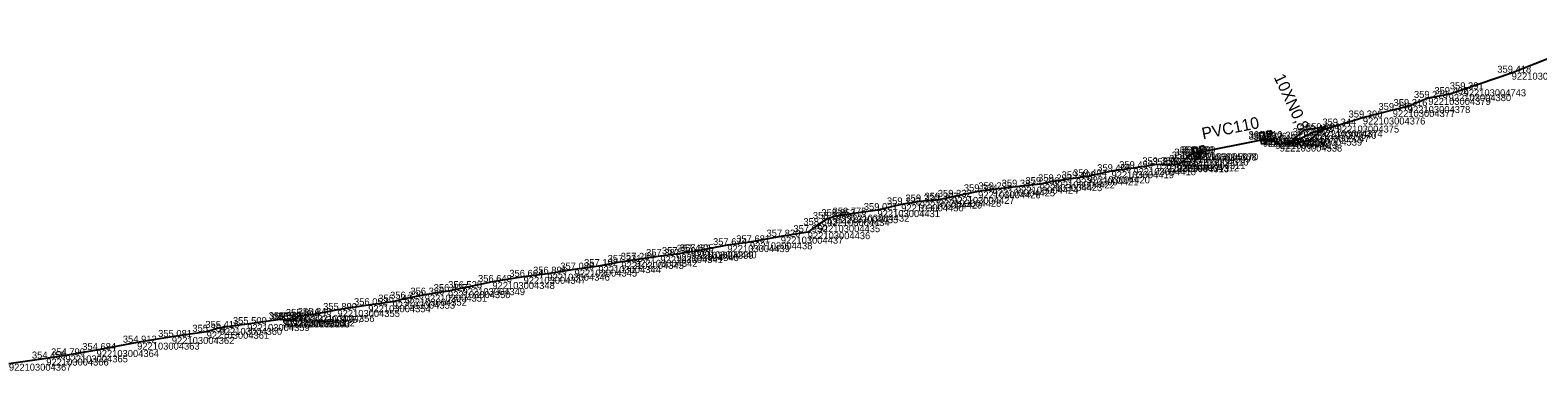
# Model space of a CAD drawing. Extents: x -771047 to -756200, y -1053876 to -1046520.
# Drawn here: x -758883.8 to -758625.3, y -1048951.2 to -1048892.8 of the extents above; entities that cross this region are included whole.
import ezdxf

# ---------------------------------------------------------------- set-up
doc = ezdxf.new("R2010")
doc.units = 0
for name, color, linetype in [('Vrstva 32', 7, 'Continuous'), ('Vrstva 33', 7, 'Continuous'), ('Vrstva 60', 7, 'Continuous'), ('Vrstva 61', 7, 'Continuous')]:
    doc.layers.add(name, color=color, linetype=linetype)

msp = doc.modelspace()

# ---------------------------------------------------------------- linework, layer by layer
at = {"layer": 'Vrstva 32'}
for points in [[(-758672.4, -1048911.57), (-758671.64, -1048911.59), (-758670.27, -1048911.96), (-758669.53, -1048912.41), (-758666.11, -1048911.41), (-758664.84, -1048910.79), (-758663.65, -1048910.24), (-758662.59, -1048909.95), (-758659.76, -1048909.15), (-758655.27, -1048907.77), (-758650.15, -1048906.48), (-758647.56, -1048905.81), (-758644.05, -1048904.41), (-758640.56, -1048903.76), (-758638, -1048902.93), (-758629.76, -1048900.09), (-758621.67, -1048896.89), (-758616.37, -1048894.81), (-758614.59, -1048893.99), (-758611.6, -1048892.79)], [(-758668.01, -1048912.27), (-758665.26, -1048909.88), (-758661.67, -1048909.31), (-758664.41, -1048911.69), (-758668.01, -1048912.27)], [(-758672.4, -1048911.57), (-758684.2, -1048913.94), (-758685.22, -1048914.3), (-758685.57, -1048914.81), (-758686.12, -1048915.4), (-758687.22, -1048915.82), (-758688.93, -1048915.95), (-758690.62, -1048915.8)], [(-758690.62, -1048915.8), (-758694.6, -1048916.46), (-758698.36, -1048916.98), (-758702.5, -1048917.86), (-758704.46, -1048918.2), (-758708.49, -1048918.72), (-758710.66, -1048919.19), (-758714.75, -1048919.63), (-758718.75, -1048920.09), (-758721.23, -1048920.43), (-758725.69, -1048921.38), (-758727.97, -1048921.88), (-758731.23, -1048922.18), (-758734.42, -1048922.67), (-758738.48, -1048923.65), (-758743.73, -1048924.43), (-758745.64, -1048924.69), (-758747.11, -1048925.17), (-758748.74, -1048926.23), (-758750.44, -1048927.43), (-758755.06, -1048928.2), (-758760.35, -1048929.17), (-758764.22, -1048929.66), (-758769.92, -1048930.72)], [(-758769.92, -1048930.72), (-758770.44, -1048930.79), (-758772.98, -1048931.19), (-758775.71, -1048931.52), (-758780.05, -1048932.17), (-758782.39, -1048932.53), (-758786.33, -1048933.25), (-758790.41, -1048933.85), (-758795.08, -1048934.55), (-758799.16, -1048935.09), (-758804.51, -1048935.97), (-758809.62, -1048937.03), (-758812.11, -1048937.54), (-758816.11, -1048938.15), (-758819.59, -1048938.84), (-758821.62, -1048939.35), (-758825.79, -1048939.96), (-758831.07, -1048940.77), (-758835.42, -1048941.62), (-758837.45, -1048941.81), (-758838.78, -1048942.39), (-758839.65, -1048942.57), (-758840.25, -1048942.56), (-758840.48, -1048942.35), (-758846.54, -1048943.19), (-758851.26, -1048943.85), (-758853.49, -1048944.51), (-758859.46, -1048945.4), (-758865.41, -1048946.37), (-758872.37, -1048947.64), (-758877.7, -1048948.56), (-758880.99, -1048949.1), (-758887.39, -1048949.99)]]:
    msp.add_lwpolyline(points, dxfattribs=at)
at = {"layer": 'Vrstva 33'}
for points in [[(-758672.98, -1048910.4), (-758672.25, -1048910.25), (-758671.86, -1048912.22), (-758672.59, -1048912.37)], [(-758684.48, -1048912.99), (-758683.75, -1048912.84), (-758683.36, -1048914.81), (-758684.09, -1048914.96)]]:
    msp.add_lwpolyline(points, close=True, dxfattribs=at)
for points in [[(-758671.74, -1048910.14), (-758671.23, -1048910.04)], [(-758671.5, -1048911.37), (-758671.74, -1048910.14)], [(-758671.23, -1048910.04), (-758671.07, -1048910.06), (-758670.92, -1048910.24), (-758670.9, -1048910.34), (-758670.96, -1048910.57), (-758671.11, -1048910.65)], [(-758672.4, -1048911.57), (-758684.2, -1048913.94)], [(-758683.24, -1048912.73), (-758682.73, -1048912.63)], [(-758683, -1048913.96), (-758683.24, -1048912.73)], [(-758682.73, -1048912.63), (-758682.57, -1048912.65), (-758682.42, -1048912.83), (-758682.4, -1048912.93), (-758682.46, -1048913.16), (-758682.61, -1048913.24)], [(-758671.11, -1048910.65), (-758671.62, -1048910.75)], [(-758682.61, -1048913.24), (-758683.12, -1048913.34)]]:
    msp.add_lwpolyline(points, dxfattribs=at)
at = {"layer": 'Vrstva 60'}
for p, q in [((-758629.76, -1048900.09), (-758629.76, -1048900.09)), ((-758644.05, -1048904.41), (-758644.05, -1048904.41)), ((-758640.56, -1048903.76), (-758640.56, -1048903.76)), ((-758638, -1048902.93), (-758638, -1048902.93)), ((-758655.27, -1048907.77), (-758655.27, -1048907.77)), ((-758650.15, -1048906.48), (-758650.15, -1048906.48)), ((-758647.56, -1048905.81), (-758647.56, -1048905.81)), ((-758663.65, -1048910.24), (-758663.65, -1048910.24)), ((-758662.59, -1048909.95), (-758662.59, -1048909.95)), ((-758659.76, -1048909.15), (-758659.76, -1048909.15)), ((-758672.42, -1048911.31), (-758672.42, -1048911.31)), ((-758672.4, -1048911.57), (-758672.4, -1048911.57)), ((-758671.64, -1048911.59), (-758671.64, -1048911.59)), ((-758670.27, -1048911.96), (-758670.27, -1048911.96)), ((-758669.53, -1048912.41), (-758669.53, -1048912.41)), ((-758666.11, -1048911.41), (-758666.11, -1048911.41)), ((-758664.84, -1048910.79), (-758664.84, -1048910.79)), ((-758686.12, -1048915.4), (-758686.12, -1048915.4)), ((-758685.57, -1048914.81), (-758685.57, -1048914.81)), ((-758685.22, -1048914.3), (-758685.22, -1048914.3)), ((-758684.2, -1048913.94), (-758684.2, -1048913.94)), ((-758683.92, -1048913.9), (-758683.92, -1048913.9)), ((-758704.46, -1048918.2), (-758704.46, -1048918.2)), ((-758702.5, -1048917.86), (-758702.5, -1048917.86)), ((-758698.36, -1048916.98), (-758698.36, -1048916.98)), ((-758694.6, -1048916.46), (-758694.6, -1048916.46)), ((-758690.62, -1048915.8), (-758690.62, -1048915.8)), ((-758688.93, -1048915.95), (-758688.93, -1048915.95)), ((-758687.22, -1048915.82), (-758687.22, -1048915.82)), ((-758721.23, -1048920.43), (-758721.23, -1048920.43)), ((-758718.75, -1048920.09), (-758718.75, -1048920.09)), ((-758714.75, -1048919.63), (-758714.75, -1048919.63)), ((-758710.66, -1048919.19), (-758710.66, -1048919.19)), ((-758708.49, -1048918.72), (-758708.49, -1048918.72)), ((-758734.42, -1048922.67), (-758734.42, -1048922.67)), ((-758731.23, -1048922.18), (-758731.23, -1048922.18)), ((-758727.97, -1048921.88), (-758727.97, -1048921.88)), ((-758725.69, -1048921.38), (-758725.69, -1048921.38)), ((-758747.11, -1048925.17), (-758747.11, -1048925.17)), ((-758745.64, -1048924.69), (-758745.64, -1048924.69)), ((-758743.73, -1048924.43), (-758743.73, -1048924.43)), ((-758738.48, -1048923.65), (-758738.48, -1048923.65)), ((-758755.06, -1048928.2), (-758755.06, -1048928.2)), ((-758750.44, -1048927.43), (-758750.44, -1048927.43)), ((-758748.74, -1048926.23), (-758748.74, -1048926.23)), ((-758770.44, -1048930.79), (-758770.44, -1048930.79)), ((-758769.92, -1048930.72), (-758769.92, -1048930.72)), ((-758764.22, -1048929.66), (-758764.22, -1048929.66)), ((-758760.35, -1048929.17), (-758760.35, -1048929.17)), ((-758786.33, -1048933.25), (-758786.33, -1048933.25)), ((-758782.39, -1048932.53), (-758782.39, -1048932.53)), ((-758780.05, -1048932.17), (-758780.05, -1048932.17)), ((-758775.71, -1048931.52), (-758775.71, -1048931.52)), ((-758772.98, -1048931.19), (-758772.98, -1048931.19)), ((-758804.51, -1048935.97), (-758804.51, -1048935.97)), ((-758799.16, -1048935.09), (-758799.16, -1048935.09)), ((-758795.08, -1048934.55), (-758795.08, -1048934.55)), ((-758790.41, -1048933.85), (-758790.41, -1048933.85)), ((-758819.59, -1048938.84), (-758819.59, -1048938.84)), ((-758816.11, -1048938.15), (-758816.11, -1048938.15)), ((-758812.11, -1048937.54), (-758812.11, -1048937.54)), ((-758809.62, -1048937.03), (-758809.62, -1048937.03)), ((-758831.07, -1048940.77), (-758831.07, -1048940.77)), ((-758825.79, -1048939.96), (-758825.79, -1048939.96)), ((-758821.62, -1048939.35), (-758821.62, -1048939.35)), ((-758851.26, -1048943.85), (-758851.26, -1048943.85)), ((-758846.54, -1048943.19), (-758846.54, -1048943.19)), ((-758840.48, -1048942.35), (-758840.48, -1048942.35)), ((-758840.25, -1048942.56), (-758840.25, -1048942.56)), ((-758839.65, -1048942.57), (-758839.65, -1048942.57)), ((-758838.78, -1048942.39), (-758838.78, -1048942.39)), ((-758837.45, -1048941.81), (-758837.45, -1048941.81)), ((-758835.42, -1048941.62), (-758835.42, -1048941.62)), ((-758865.41, -1048946.37), (-758865.41, -1048946.37)), ((-758859.46, -1048945.4), (-758859.46, -1048945.4)), ((-758853.49, -1048944.51), (-758853.49, -1048944.51)), ((-758880.99, -1048949.1), (-758880.99, -1048949.1)), ((-758877.7, -1048948.56), (-758877.7, -1048948.56)), ((-758872.37, -1048947.64), (-758872.37, -1048947.64))]:
    msp.add_line(p, q, dxfattribs=at)

# ---------------------------------------------------------------- texts
at = {"layer": 'Vrstva 32'}
msp.add_text('10XN0,8', height=2, rotation=295.054, dxfattribs=at).set_placement((-758670.58, -1048900.84))
at = {"layer": 'Vrstva 33'}
msp.add_text('PVC110', height=2, rotation=11.3799, dxfattribs=at).set_placement((-758682.67, -1048911.53))
at = {"layer": 'Vrstva 60'}
for s, p in [('922103004744', (-758629.76, -1048901.29)), ('922103004379', (-758644.05, -1048905.61)), ('922103004380', (-758640.56, -1048904.96)), ('922103004743', (-758638, -1048904.13)), ('922103004376', (-758655.27, -1048908.97)), ('922103004377', (-758650.15, -1048907.68)), ('922103004378', (-758647.56, -1048907.01)), ('922103004540', (-758663.65, -1048911.44)), ('922103004374', (-758662.59, -1048911.15)), ('922103004375', (-758659.76, -1048910.35)), ('922103005069', (-758672.42, -1048912.51)), ('922103004307', (-758672.4, -1048912.77)), ('922103004812', (-758671.64, -1048912.79)), ('922103004813', (-758670.27, -1048913.16)), ('922103004538', (-758669.53, -1048913.61)), ('922103004539', (-758666.11, -1048912.6)), ('922103005047', (-758664.84, -1048911.99)), ('922103004311', (-758686.12, -1048916.6)), ('922103004310', (-758685.57, -1048916.01)), ('922103004309', (-758685.22, -1048915.5)), ('922103004308', (-758684.2, -1048915.14)), ('922103005070', (-758683.92, -1048915.1)), ('922103004421', (-758704.46, -1048919.4)), ('922103004420', (-758702.5, -1048919.06)), ('922103004419', (-758698.36, -1048918.18)), ('922103004418', (-758694.6, -1048917.66)), ('922103004417', (-758690.62, -1048917)), ('922103004313', (-758688.93, -1048917.15)), ('922103004312', (-758687.22, -1048917.02)), ('922103004426', (-758721.23, -1048921.63)), ('922103004425', (-758718.75, -1048921.29)), ('922103004424', (-758714.75, -1048920.83)), ('922103004423', (-758710.66, -1048920.39)), ('922103004422', (-758708.49, -1048919.92)), ('922103004430', (-758734.42, -1048923.87)), ('922103004429', (-758731.23, -1048923.38)), ('922103004428', (-758727.97, -1048923.08)), ('922103004427', (-758725.69, -1048922.58)), ('922103004434', (-758747.11, -1048926.37)), ('922103004433', (-758745.64, -1048925.89)), ('922103004432', (-758743.73, -1048925.62)), ('922103004431', (-758738.48, -1048924.85)), ('922103004437', (-758755.06, -1048929.4)), ('922103004436', (-758750.44, -1048928.63)), ('922103004435', (-758748.74, -1048927.43)), ('922103004339', (-758770.44, -1048931.99)), ('922103004440', (-758769.92, -1048931.92)), ('922103004439', (-758764.22, -1048930.85)), ('922103004438', (-758760.35, -1048930.37)), ('922103004344', (-758786.33, -1048934.45)), ('922103004343', (-758782.39, -1048933.73)), ('922103004342', (-758780.05, -1048933.37)), ('922103004341', (-758775.71, -1048932.72)), ('922103004340', (-758772.98, -1048932.39)), ('922103004348', (-758804.51, -1048937.17)), ('922103004347', (-758799.16, -1048936.29)), ('922103004346', (-758795.08, -1048935.75)), ('922103004345', (-758790.41, -1048935.05)), ('922103004352', (-758819.59, -1048940.04)), ('922103004351', (-758816.11, -1048939.35)), ('922103004350', (-758812.11, -1048938.74)), ('922103004349', (-758809.62, -1048938.23)), ('922103004355', (-758831.07, -1048941.97)), ('922103004354', (-758825.79, -1048941.16)), ('922103004353', (-758821.62, -1048940.55)), ('922103004360', (-758851.26, -1048945.05)), ('922103004359', (-758846.54, -1048944.39)), ('922103004358', (-758840.48, -1048943.55)), ('922103005004', (-758840.25, -1048943.76)), ('922103005003', (-758839.65, -1048943.77)), ('922103005002', (-758838.78, -1048943.59)), ('922103004357', (-758837.45, -1048943.01)), ('922103004356', (-758835.42, -1048942.82)), ('922103004363', (-758865.41, -1048947.57)), ('922103004362', (-758859.46, -1048946.6)), ('922103004361', (-758853.49, -1048945.71)), ('922103004366', (-758880.99, -1048950.3)), ('922103004365', (-758877.7, -1048949.76)), ('922103004364', (-758872.37, -1048948.84)), ('922103004367', (-758887.39, -1048951.19))]:
    msp.add_text(s, height=1.2, dxfattribs=at).set_placement(p)
at = {"layer": 'Vrstva 61'}
for s, p in [('359.418', (-758632.22, -1048900.09)), ('359.402', (-758643.01, -1048903.76)), ('359.391', (-758640.36, -1048902.93)), ('359.346', (-758652.6, -1048906.48)), ('359.316', (-758650.01, -1048905.81)), ('359.273', (-758646.51, -1048904.41)), ('359.396', (-758657.72, -1048907.77)), ('360.410', (-758674.87, -1048911.31)), ('358.977', (-758674.85, -1048911.57)), ('358.926', (-758674.09, -1048911.59)), ('359.530', (-758668.56, -1048911.41)), ('360.025', (-758667.29, -1048910.79)), ('359.452', (-758666.1, -1048910.24)), ('359.384', (-758665.04, -1048909.95)), ('359.344', (-758662.21, -1048909.15)), ('358.870', (-758686.65, -1048913.94)), ('360.380', (-758686.37, -1048913.9)), ('358.941', (-758672.63, -1048911.96)), ('359.375', (-758671.99, -1048912.41)), ('359.450', (-758697.05, -1048916.46)), ('359.383', (-758693.08, -1048915.8)), ('358.669', (-758691.38, -1048915.95)), ('358.691', (-758689.58, -1048915.82)), ('358.921', (-758688.48, -1048915.4)), ('358.880', (-758688.02, -1048914.81)), ('358.871', (-758687.58, -1048914.3)), ('359.206', (-758713.11, -1048919.19)), ('359.293', (-758710.95, -1048918.72)), ('359.400', (-758706.91, -1048918.2)), ('359.404', (-758704.95, -1048917.86)), ('359.408', (-758700.81, -1048916.98)), ('359.307', (-758730.42, -1048921.88)), ('359.332', (-758728.14, -1048921.38)), ('359.334', (-758723.68, -1048920.43)), ('359.295', (-758721.2, -1048920.09)), ('359.387', (-758717.2, -1048919.63)), ('358.775', (-758746.18, -1048924.43)), ('359.021', (-758740.83, -1048923.65)), ('359.122', (-758736.87, -1048922.67)), ('359.220', (-758733.68, -1048922.18)), ('358.343', (-758751.19, -1048926.23)), ('358.733', (-758749.56, -1048925.17)), ('358.853', (-758748.09, -1048924.69)), ('357.674', (-758766.68, -1048929.66)), ('357.681', (-758762.7, -1048929.17)), ('357.820', (-758757.51, -1048928.2)), ('357.950', (-758752.89, -1048927.43)), ('357.284', (-758782.5, -1048932.17)), ('357.387', (-758778.16, -1048931.52)), ('357.369', (-758775.44, -1048931.19)), ('357.453', (-758772.89, -1048930.79)), ('357.605', (-758772.37, -1048930.72)), ('356.896', (-758797.53, -1048934.55)), ('357.089', (-758792.87, -1048933.85)), ('357.192', (-758788.78, -1048933.25)), ('357.231', (-758784.75, -1048932.53)), ('356.528', (-758812.08, -1048937.03)), ('356.648', (-758806.97, -1048935.97)), ('356.664', (-758801.61, -1048935.09)), ('356.052', (-758828.23, -1048939.96)), ('356.143', (-758824.07, -1048939.35)), ('356.220', (-758822.04, -1048938.84)), ('356.380', (-758818.56, -1048938.15)), ('356.427', (-758814.57, -1048937.54)), ('355.581', (-758842.84, -1048942.35)), ('356.153', (-758842.7, -1048942.56)), ('355.644', (-758842.1, -1048942.57)), ('355.536', (-758841.23, -1048942.39)), ('355.846', (-758839.91, -1048941.81)), ('355.840', (-758837.87, -1048941.62)), ('355.890', (-758833.52, -1048940.77)), ('355.254', (-758855.94, -1048944.51)), ('355.416', (-758853.71, -1048943.85)), ('355.500', (-758848.99, -1048943.19)), ('354.684', (-758874.82, -1048947.64)), ('354.912', (-758867.86, -1048946.37)), ('355.081', (-758861.81, -1048945.4)), ('354.455', (-758883.45, -1048949.1)), ('354.790', (-758880.16, -1048948.56))]:
    msp.add_text(s, height=1.2, dxfattribs=at).set_placement(p)

doc.saveas('drawing.dxf')
